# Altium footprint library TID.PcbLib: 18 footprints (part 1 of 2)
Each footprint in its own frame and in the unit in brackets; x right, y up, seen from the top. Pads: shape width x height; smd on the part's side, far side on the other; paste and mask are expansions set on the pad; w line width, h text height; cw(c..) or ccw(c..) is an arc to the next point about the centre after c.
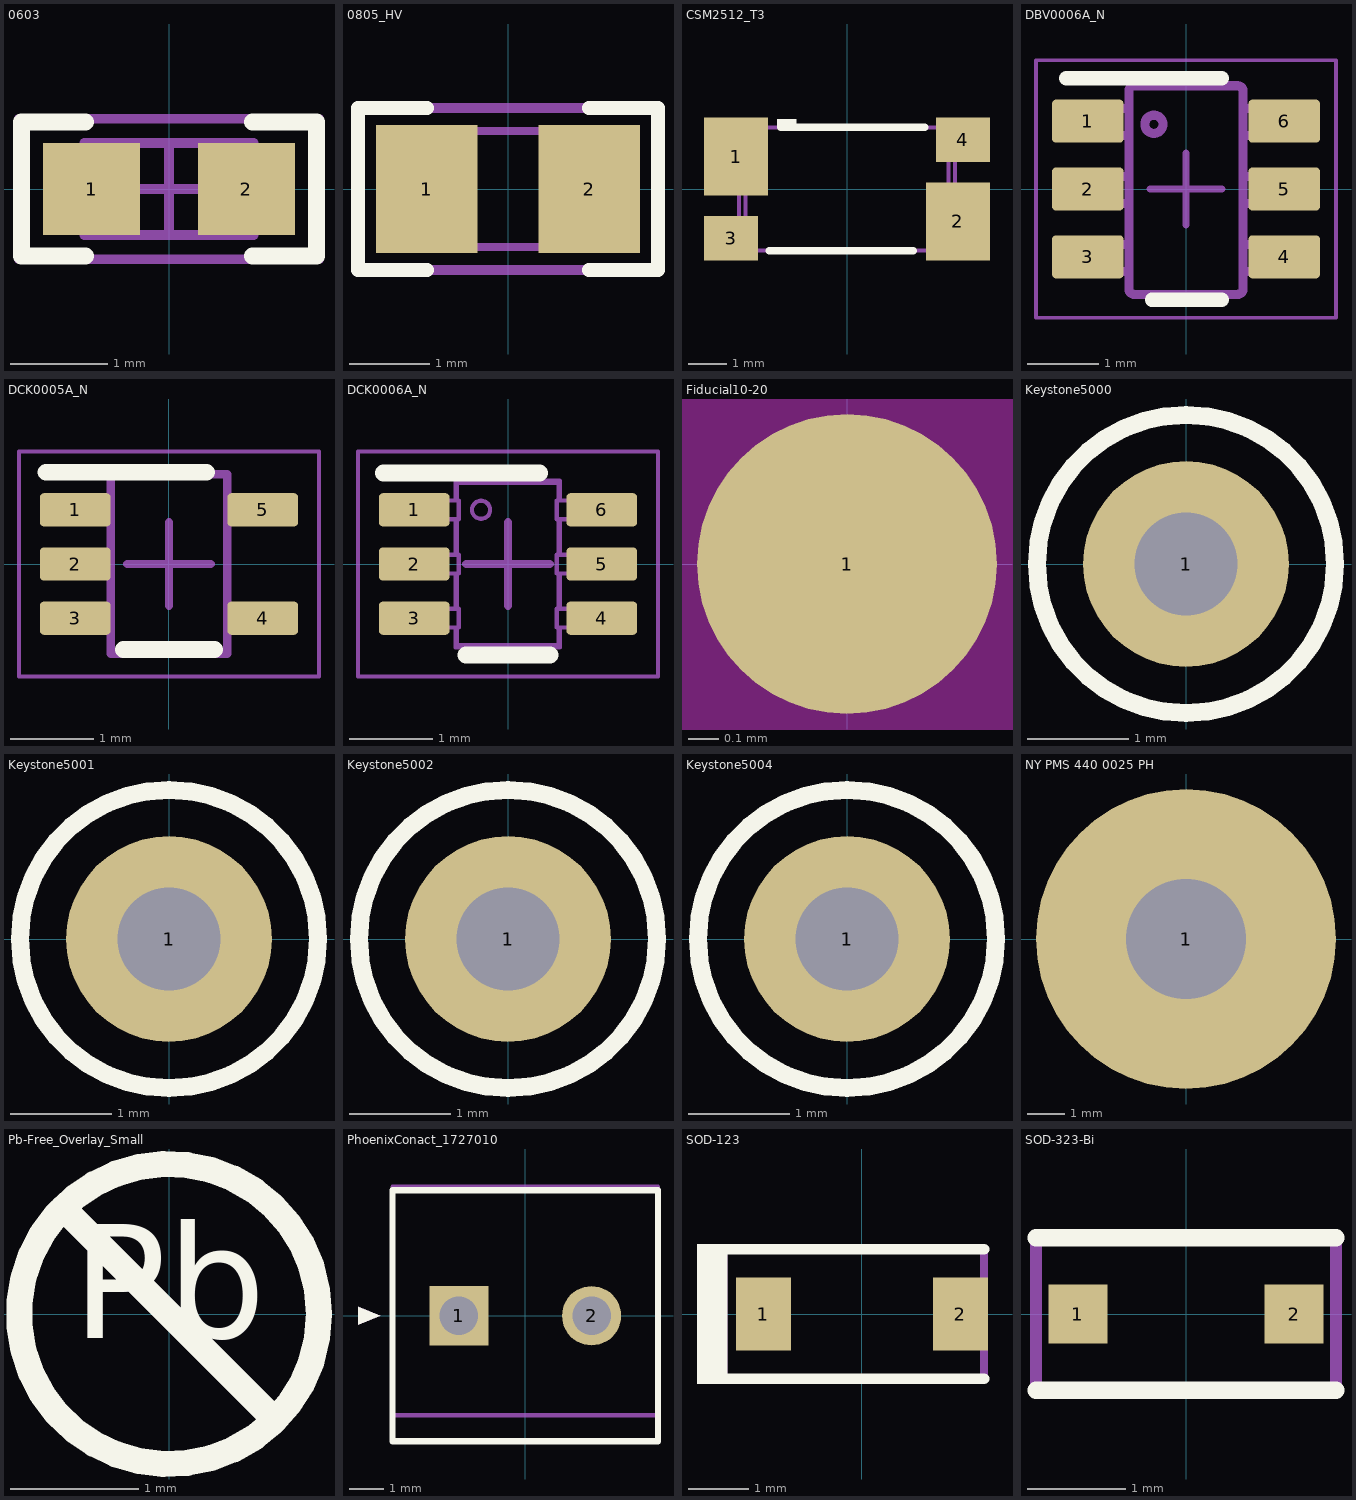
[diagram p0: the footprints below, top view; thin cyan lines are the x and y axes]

## 0603 [mm] "0603 from SM-752 data"
height 1
pads (2):
  rect 1x0.95 smd: 1(-0.8,0) 2(0.8,0)
Top Overlay:
  lines w0.178: -0.864,-0.691 -1.524,-0.691 -1.524,0.693 -0.864,0.693 ; 0.864,-0.691 1.524,-0.691 1.524,0.693 0.864,0.693
Mechanical 5:
  lines w0.1: -1.55,-0.725 -1.55,0.725 1.55,0.725 1.55,-0.725 -1.55,-0.725
  text ".Designator" at -1.397,-0.381 h0.76
Mechanical 13:
  lines w0.1: -0.55,-0.475 -0.55,0.475 ; 0.55,-0.475 0.55,0.475 ; -0.875,-0.475 0.875,-0.475 0.875,0.475 -0.875,0.475 -0.875,-0.475
Mechanical 15:
  lines w0.1: -0.475,0 0.475,0 ; 0,-0.475 0,0.475 ; -1.55,-0.725 1.55,-0.725 1.55,0.725 -1.55,0.725 -1.55,-0.725
3D body: height 1, standoff 0, extent -0.874,-0.474 -0.551,0.474
3D body: height 1, standoff 0, extent -0.549,-0.474 0.549,0.474
3D body: height 1, standoff 0, extent 0.551,-0.474 0.874,0.474

## 0805_HV [mil] "0805 with 30mil clearance between pads"
height 57.09
pads (2):
  rect 50x63 smd: 1(-40,0) 2(40,0)
Top Overlay:
  lines w7: -40,-40 -74,-40 -74,0 -74,40 -40,40 ; 40,-40 74,-40 74,0 74,40 40,40
Mechanical 5:
  lines w5: -74,-40 74,-40 74,40 -74,40 -74,-40
  text ".Designator" at -64,-17 h35
Mechanical 13:
  lines w3.94: -25.59,-28.54 -25.59,28.54 ; 25.59,-28.54 25.59,28.54 ; -43.31,-28.54 43.31,-28.54 43.31,28.54 -43.31,28.54 -43.31,-28.54
3D body: height 57.09, standoff 0, extent -43.29,-28.52 -25.61,28.52
3D body: height 57.09, standoff 0, extent -25.57,-28.52 25.57,28.52
3D body: height 57.09, standoff 0, extent 25.61,-28.52 43.29,28.52

## CSM2512_T3 [mm] "SMD, 4-Leads, Body 6.35x3.175mm"
height 0.889
pads (4):
  rect 1.65x2.01 smd: 1(-2.855,0.835) 2(2.855,-0.835)
  rect 1.39x1.14 smd: 3(-2.985,-1.27) 4(2.985,1.27)
Top Overlay:
  rectangle: -1.8,1.587 -1.3,1.8
  lines w0.2: -2,-1.588 1.7,-1.588 ; -1.7,1.587 2,1.587
Mechanical 5:
  drawing of 520 lines, arcs and shapes, not listed
  text ".Designator" at -1.8,-0.5 h1.02
3D body: height 0.7, standoff 0, extent -3.175,-1.587 3.175,1.588

## DBV0006A_N [mm] "SOT23, 6-Leads, Body 2.9x1.6mm, Pitch 0.95mm, Lead Span 2.8mm, IPC Medium Density"
height 1.45
pads (6):
  rrect17% 1x0.6 smd: 1(-1.375,0.95) 2(-1.375,0) 3(-1.375,-0.95) 4(1.375,-0.95) 5(1.375,0) 6(1.375,0.95)
Top Overlay:
  lines w0.2: -1.675,1.55 0.5,1.55 ; -0.475,-1.55 0.5,-1.55
Mechanical 5:
  lines w0.127: 0.724,-1.475 ccw(c0.723,-1.399) 0.8,-1.399 0.8,1.37 ccw(c0.723,1.37) 0.724,1.446 ; 0.723,-1.475 0.724,-1.475 ; 0.723,-1.475 -0.724,-1.475 -0.725,-1.475 cw(c-0.724,-1.399) -0.801,-1.399 -0.801,1.37 cw(c-0.724,1.37) -0.725,1.446 -0.724,1.446 0.723,1.446 ; 0.723,1.446 0.724,1.446 ; -1.423,-1.154 -1.206,-1.154 -1.113,-1.154 -1.081,-1.154 -0.828,-1.154 -0.801,-1.154 -0.801,-0.78 -0.828,-0.78 -1.081,-0.78 -1.113,-0.78 -1.206,-0.78 -1.423,-0.78 -1.423,-1.154 ; -1.423,-0.202 -1.206,-0.202 -1.113,-0.202 -1.081,-0.202 -0.828,-0.202 -0.801,-0.202 -0.801,0.173 -0.828,0.173 -1.081,0.173 -1.113,0.173 -1.206,0.173 -1.423,0.173 -1.423,-0.202 ; -1.423,0.751 -1.206,0.751 -1.113,0.751 -1.081,0.751 -0.828,0.751 -0.801,0.751 -0.801,1.125 -0.828,1.125 -1.081,1.125 -1.113,1.125 -1.206,1.125 -1.423,1.125 -1.423,0.751 ; -0.577,0.906 cw(c-0.45,0.906) -0.323,0.906 cw(c-0.45,0.906) -0.577,0.906 ; 0.8,-1.154 0.827,-1.154 1.08,-1.154 1.112,-1.154 1.205,-1.154 1.422,-1.154 1.422,-0.78 1.205,-0.78 1.112,-0.78 1.08,-0.78 0.827,-0.78 0.8,-0.78 0.8,-1.154 ; 0.8,-0.202 0.827,-0.202 1.08,-0.202 1.112,-0.202 1.205,-0.202 1.422,-0.202 1.422,0.173 1.205,0.173 1.112,0.173 1.08,0.173 0.827,0.173 0.8,0.173 0.8,-0.202 ; 0.8,0.751 0.827,0.751 1.08,0.751 1.112,0.751 1.205,0.751 1.422,0.751 1.422,1.125 1.205,1.125 1.112,1.125 1.08,1.125 0.827,1.125 0.8,1.125 0.8,0.751
  text ".Designator" at -0.075,0.925 h0.51
Mechanical 15:
  lines w0.05: -2.1,-1.8 2.1,-1.8 2.1,1.8 -2.1,1.8 -2.1,-1.8
  lines w0.1: -0.5,0 0.5,0 ; 0,-0.5 0,0.5
3D body: height 1.12, standoff 0, extent -1.422,-1.461 1.423,1.46

## DCK0005A_N [mm] "SOT353, 5-Leads, Body 2x1.3mm, Pitch 0.65mm, Lead Span 2.1mm, IPC Medium Density"
height 1.1
pads (5):
  rrect25% 0.85x0.4 smd: 1(-1.125,0.65) 2(-1.125,0) 3(-1.125,-0.65) 4(1.125,-0.65) 5(1.125,0.65)
Top Overlay:
  lines w0.2: -1.475,1.1 0.45,1.1 ; -0.55,-1.025 0.55,-1.025
Mechanical 5:
  lines w0.1: -0.7,-1.075 -0.7,1.075 0.7,1.075 0.7,-1.075 -0.7,-1.075
  lines w0.127: -0.865,0.762 -0.853,0.762 ; -0.711,-0.763 -0.853,-0.763 -0.865,-0.763 -0.959,-0.763 -1.143,-0.763 -1.143,-0.538 -0.959,-0.538 -0.865,-0.538 -0.853,-0.538 -0.711,-0.538 ; -0.711,-0.113 -0.853,-0.113 -0.865,-0.113 -0.959,-0.113 -1.143,-0.113 -1.143,0.112 -0.959,0.112 -0.865,0.112 -0.853,0.112 -0.711,0.112 ; -0.711,0.537 -0.853,0.537 -0.865,0.537 -0.959,0.537 -1.143,0.537 -1.143,0.762 -0.959,0.762 -0.711,0.762 ; 0.711,-0.763 0.847,-0.763 0.859,-0.763 0.953,-0.763 1.137,-0.763 1.137,-0.538 0.953,-0.538 0.859,-0.538 0.847,-0.538 0.711,-0.538 ; 0.711,0.537 0.847,0.537 0.859,0.537 0.953,0.537 1.137,0.537 1.137,0.762 0.953,0.762 0.859,0.762 0.847,0.762 0.711,0.762
  text ".Designator" at -0.254,0.914 h0.51
Mechanical 15:
  lines w0.05: -1.8,-1.35 -1.8,1.35 1.8,1.35 1.8,-1.35 -1.8,-1.35
  lines w0.1: -0.5,0 0.5,0 ; 0,-0.5 0,0.5
3D body: height 0.95, standoff 0, extent -1.14,-1 1.14,1

## DCK0006A_N [mm] "SOT23, 6-Leads, Body 2x1.3mm, Pitch 0.65mm, Lead Span 2.1mm, IPC Medium Density"
height 1.1
pads (6):
  rrect25% 0.85x0.4 smd: 1(-1.125,0.65) 2(-1.125,0) 3(-1.125,-0.65) 4(1.125,-0.65) 5(1.125,0) 6(1.125,0.65)
Top Overlay:
  lines w0.2: -1.499,1.092 0.381,1.092 ; -0.508,-1.092 0.508,-1.092
Mechanical 5:
  lines w0.05: -0.613,-0.763 -0.613,-0.976 0.607,-0.976 0.607,-0.763 ; -0.613,-0.538 -0.613,-0.113 ; -0.613,0.112 -0.613,0.537 ; -0.613,0.762 -0.613,0.974 0.607,0.974 0.607,0.762 ; 0.607,-0.538 0.607,-0.113 ; 0.607,0.112 0.607,0.537 ; -0.628,-0.763 -0.628,-1.001 0.622,-1.001 0.622,-0.763 ; -0.628,-0.763 -0.853,-0.763 -0.865,-0.763 -0.959,-0.763 -1.143,-0.763 -1.143,-0.538 -0.959,-0.538 -0.865,-0.538 -0.853,-0.538 -0.628,-0.538 ; -0.628,-0.763 -0.591,-0.763 -0.591,-0.538 -0.628,-0.538 ; -0.628,-0.538 -0.628,-0.113 ; -0.628,-0.113 -0.853,-0.113 -0.865,-0.113 -0.959,-0.113 -1.143,-0.113 -1.143,0.112 -0.959,0.112 -0.865,0.112 -0.853,0.112 -0.628,0.112 ; -0.628,-0.113 -0.591,-0.113 -0.591,0.112 -0.628,0.112 ; -0.628,0.112 -0.628,0.537 ; -0.628,0.537 -0.853,0.537 -0.865,0.537 -0.959,0.537 -1.143,0.537 -1.143,0.762 -0.959,0.762 -0.865,0.762 -0.853,0.762 -0.628,0.762 ; -0.628,0.537 -0.591,0.537 -0.591,0.762 -0.628,0.762 ; -0.628,0.762 -0.628,0.999 0.622,0.999 0.622,0.762 ; 0.622,-0.763 0.847,-0.763 0.859,-0.763 0.953,-0.763 1.137,-0.763 1.137,-0.538 0.953,-0.538 0.859,-0.538 0.847,-0.538 0.622,-0.538 ; 0.622,-0.763 0.585,-0.763 0.585,-0.538 0.622,-0.538 ; 0.622,-0.538 0.622,-0.113 ; 0.622,-0.113 0.585,-0.113 0.585,0.112 0.622,0.112 ; 0.622,-0.113 0.847,-0.113 0.859,-0.113 0.953,-0.113 1.137,-0.113 1.137,0.112 0.953,0.112 0.859,0.112 0.847,0.112 0.622,0.112 ; 0.622,0.112 0.622,0.537 ; 0.622,0.537 0.847,0.537 0.859,0.537 0.953,0.537 1.137,0.537 1.137,0.762 0.953,0.762 0.859,0.762 0.847,0.762 0.622,0.762 ; 0.622,0.537 0.585,0.537 0.585,0.762 0.622,0.762 ; -0.432,0.65 cw(c-0.323,0.65) -0.215,0.65 cw(c-0.323,0.65) -0.432,0.65
  text ".Designator" at -0.051,0.66 h0.38
Mechanical 15:
  lines w0.05: -1.8,-1.35 -1.8,1.35 1.8,1.35 1.8,-1.35 -1.8,-1.35
  lines w0.1: -0.5,0 0.5,0 ; 0,-0.5 0,0.5
3D body: height 0.95, standoff 0, extent -1.14,-1 1.14,1

## Fiducial10-20 [mm]
pads (1):
  round 1 smd mask+0.5: 1(0,0)
Top Layer keep-out:
  circle w1.178: c0,0 r0.5

## Keystone5000 [mil] "For Keystone 500x miniature loop terminals"
height 181.1
pads (1):
  round 80 hole 40: 1(0,0)
Top Overlay:
  circle w7: c0,0 r58
Mechanical 5:
  circle w5: c0,0 r58.31
  text ".Designator" at -45,-10 h30
3D body: height 181.97, standoff -118.11, extent -49,-49 49.04,49.24

## Keystone5001 [mil] "For Keystone 500x miniature loop terminals"
height 181.1
pads (1):
  round 80 hole 40: 1(0,0)
Top Overlay:
  circle w7: c0,0 r58
Mechanical 5:
  circle w5: c0,0 r58.31
  text ".Designator" at -45,-10 h30
3D body: height 181.97, standoff -118.11, extent -49,-49 49.04,49.24

## Keystone5002 [mil] "For Keystone 500x miniature loop terminals"
height 181.1
pads (1):
  round 80 hole 40: 1(0,0)
Top Overlay:
  circle w7: c0,0 r58
Mechanical 5:
  circle w5: c0,0 r58.31
  text ".Designator" at -45,-10 h30
3D body: height 181.97, standoff -118.11, extent -49,-49 49.04,49.23

## Keystone5004 [mil] "For Keystone 500x miniature loop terminals"
height 181.1
pads (1):
  round 80 hole 40: 1(0,0)
Top Overlay:
  circle w7: c0,0 r58
Mechanical 5:
  circle w5: c0,0 r58.31
  text ".Designator" at -45,-10 h30
3D body: height 181.97, standoff -118.11, extent -49,-49 49.04,49.24

## NY PMS 440 0025 PH [mm] "4-40 nylon screw and mounting hole"
height 1.905
pads (1):
  round 8 hole 3.2: 1(0,0)
Mechanical 5:
  circle w0.127: c0,0 r3.789
  text ".Designator" at -1.524,-0.508 h1.02
3D body: height 2.69, standoff -8.74, extent -3.302,-3.3 3.296,3.3

## Pb-Free_Overlay_Small [mm]
Top Overlay:
  circle w0.203: c0,0 r1.168
  lines w0.203: -0.826,0.826 0.826,-0.826
  text "Pb" at -0.752,-0.48 h1.52

## PhoenixConact_1727010 [mm]
height 8.5
pads (2):
  rect 1.7x1.7 hole 1.1: 1(-1.905,0)
  round 1.7 hole 1.1: 2(1.905,0)
Top Overlay:
  region: -4.8,-0.254 -4.8,0.254 -4.165,0
  lines w0.178: -3.81,-3.6 0,-3.6 3.81,-3.6 3.81,0 3.81,3.6 0,3.6 -3.81,3.6 -3.81,0 -3.81,-3.6
Mechanical 5:
  region: -4.8,-0.254 -4.8,0.254 -4.165,0
  lines w0.127: -3.81,-2.861 3.81,-2.861 ; -3.81,-2.861 -3.81,-3.3 -3.81,-3.6 3.81,-3.6 3.81,-3.3 3.81,-2.861 ; -3.81,-2.861 -3.81,-2.049 -3.81,-1.566 -3.81,1.487 -3.81,1.962 -3.81,3.7 3.81,3.7 3.81,1.962 3.81,1.487 3.81,-1.566 3.81,-2.049 3.81,-2.861
  text ".Designator" at -1.524,-0.508 h1.02
3D body: height 8.52, standoff -3.48, extent -3.81,-3.599 3.81,3.701

## SOD-123 [mm] "On Semi recommended land pattern"
height 1.35
pads (2):
  rect 0.915x1.22 smd: 1(-1.637,0) 2(1.637,0)
Top Overlay:
  rectangle: -2.743,-1.168 -2.235,1.168
  lines w0.178: -2.413,-1.079 2.032,-1.079 ; -2.413,1.079 2.032,1.079
Mechanical 5:
  rectangle: -2.743,-1.168 -2.235,1.168
  lines w0.127: -2.413,-1.079 2.032,-1.079 2.032,1.079 -2.413,1.079
  text ".Designator" at -1.956,-0.33 h0.76
3D body: height 1.35, standoff 0, extent -1.932,-0.9 1.932,0.9

## SOD-323-Bi [mm] "SOD323, 2-Leads, Body 1.9x1.45mm, No Polarity Mark"
height 1.1
pads (2):
  rect 0.6x0.6 smd paste-0.05: 1(-1.1,0) 2(1.1,0)
Top Overlay:
  lines w0.178: -1.525,-0.775 0.1,-0.775 1.525,-0.775 ; -1.525,0.775 0.1,0.775 1.525,0.775
Mechanical 5:
  lines w0.127: -1.525,-0.775 -1.525,0.775 0.1,0.775 1.525,0.775 1.525,-0.775 0.1,-0.775 -1.525,-0.775
  text ".Designator" at -1.4,-0.275 h0.76
3D body: height 1.02, standoff 0.01, extent -1.273,-0.65 1.273,0.65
